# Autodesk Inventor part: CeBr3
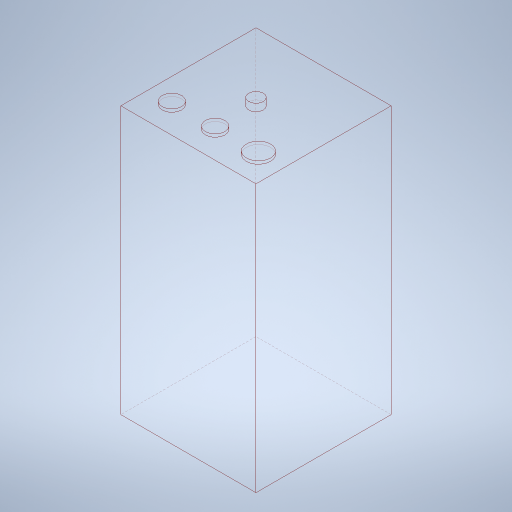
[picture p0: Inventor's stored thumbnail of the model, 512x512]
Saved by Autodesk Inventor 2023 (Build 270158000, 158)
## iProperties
Created: 2023-10
Part Number: CeBr3
Material: Aluminum
Document SubType Name: Modeling
Designer: tornqvih
Density: 2.7 g/cm^3
Appearance: Light Red
Author: tornqvih
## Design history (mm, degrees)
sketch "Sketch1"
  geometry: L1 (27.8, 27.8)-(-27.8, 27.8); L2 (-27.8, 27.8)-(-27.8, -27.8); L3 (-27.8, -27.8)-(27.8, -27.8); L4 (27.8, -27.8)-(27.8, 27.8); L5 (27.8, 27.8)-(-27.8, -27.8); L6 (-27.8, 27.8)-(27.8, -27.8); 1 further point
  constraints: 12 end point, 2 midpoint, 2 parallel, 2 perpendicular, 1 horizontal
  dimensions: "d0" = 55.6 distance of L3.end L1.start
extrude "Extrusion1" new body sketch "Sketch1" distance "d1" = 110; taper "d2" = 0 deg
sketch "Sketch2"
  geometry: C1 r 3 at (0, 0); 1 further point
  constraints: 1 centre point, 1 coincident
  dimensions: "d3" = 6 diameter of C1
extrude "Extrusion2" join sketch "Sketch2" distance "d4" = 3; taper "d5" = 0 deg
sketch "Sketch3"
  geometry: L1 (-27.8, -27.8)-(27.8, -27.8) reference; L2 (-27.8, 27.8)-(-27.8, -27.8) reference; L3 (0, 38.92)-(0, -38.92) reference; C1 r 4 at (-17.8, -16.8); C2 r 4 at (0, -16.8); C3 r 5 at (17.8, -16.8); 1 further point
  constraints: 3 centre point, 1 horizontal alignment, 1 point on line, 1 symmetric about line
  dimensions: "d6" = 8 diameter of C1; "d7" = 8 diameter of C2; "d8" = 10 diameter of C3; "d9" = 11 distance from line of L1 C2.centre; "d10" = 10 distance from line of L2 C1.centre
extrude "Extrusion3" join sketch "Sketch3" distance "d11" = 1.2; taper "d12" = 0 deg
body "Solid1"
